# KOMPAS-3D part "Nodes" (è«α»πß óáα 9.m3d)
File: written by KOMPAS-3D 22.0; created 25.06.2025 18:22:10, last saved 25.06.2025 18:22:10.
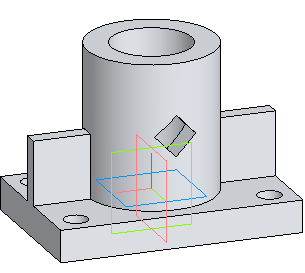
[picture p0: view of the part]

Document properties: Автор: Helen; Полное имя файла: D:\MY\WORK\MPEI\ППЭ_2025-2026\Варианты\Вар 9 СБ\Корпус вар 9.m3d

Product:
- Part/product: Nodes

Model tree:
1. Операция без истории:1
